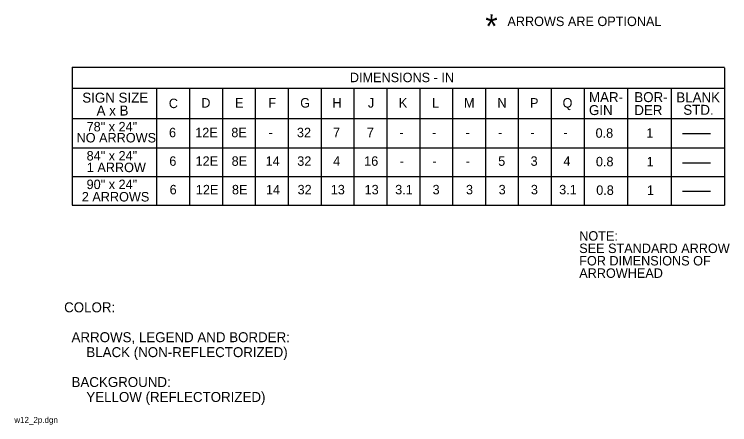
# Model space of a CAD drawing. Extents: x 0.013 to 0.2, y 0.004 to 0.259.
# Drawn here: x 0.0126 to 0.1921, y 0.0039 to 0.1069 of the extents above; entities that cross this region are included whole.
import ezdxf

# ---------------------------------------------------------------- set-up
doc = ezdxf.new("R2010")
doc.units = 0
doc.layers.add('1', color=7, linetype='Continuous')
doc.layers.add('3', color=7, linetype='Continuous')

msp = doc.modelspace()

# ---------------------------------------------------------------- linework, layer by layer
at = {"layer": '1'}
for p, q in [((0.1802803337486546, 0.07695145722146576), (0.18728598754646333, 0.07695145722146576)), ((0.1802803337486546, 0.069656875), (0.18728598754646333, 0.069656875)), ((0.1802803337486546, 0.06249062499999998), (0.18728598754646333, 0.06249062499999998))]:
    msp.add_line(p, q, dxfattribs=at)
at = {"layer": '3'}
for p, q in [((0.02711153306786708, 0.09362537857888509), (0.02711153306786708, 0.05903539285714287)), ((0.02711153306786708, 0.09362537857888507), (0.19078375, 0.09362537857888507)), ((0.19078375, 0.09343509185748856), (0.19078375, 0.05903539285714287)), ((0.19078375, 0.08824059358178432), (0.02711153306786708, 0.08824059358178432)), ((0.048336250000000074, 0.08824059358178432), (0.048336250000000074, 0.05903539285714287)), ((0.056586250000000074, 0.08824059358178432), (0.056586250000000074, 0.05903539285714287)), ((0.06483625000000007, 0.08824059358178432), (0.06483625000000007, 0.05903539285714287)), ((0.07308625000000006, 0.08824059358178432), (0.07308625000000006, 0.05903539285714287)), ((0.08133625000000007, 0.08824059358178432), (0.08133625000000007, 0.05903539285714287)), ((0.08958625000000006, 0.08824059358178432), (0.08958625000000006, 0.05903539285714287)), ((0.09783625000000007, 0.08824059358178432), (0.09783625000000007, 0.05903539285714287)), ((0.10608625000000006, 0.08824059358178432), (0.10608625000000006, 0.05903539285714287)), ((0.11433625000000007, 0.08824059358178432), (0.11433625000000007, 0.05903539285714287)), ((0.12258625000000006, 0.08824059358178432), (0.12258625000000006, 0.05903539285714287)), ((0.13083625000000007, 0.08824059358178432), (0.13083625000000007, 0.05903539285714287)), ((0.13908625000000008, 0.08824059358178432), (0.13908625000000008, 0.05903539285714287)), ((0.14733625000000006, 0.08824059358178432), (0.14733625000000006, 0.05903539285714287)), ((0.15558625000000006, 0.08824059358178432), (0.15558625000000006, 0.05903539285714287)), ((0.16646614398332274, 0.08824059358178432), (0.16646614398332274, 0.05903539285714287)), ((0.17739931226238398, 0.08824059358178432), (0.17739931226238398, 0.05903539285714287)), ((0.02711153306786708, 0.08074164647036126), (0.19078375, 0.08074164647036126)), ((0.02711153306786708, 0.07336664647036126), (0.19078374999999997, 0.07336664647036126)), ((0.02711153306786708, 0.06620101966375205), (0.19078375, 0.06620101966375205)), ((0.02711153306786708, 0.05903539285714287), (0.19078375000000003, 0.05903539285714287))]:
    msp.add_line(p, q, dxfattribs=at)

# ---------------------------------------------------------------- texts
at = {"layer": '1'}
for s, height, p in [('COLOR:', 0.0024997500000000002, (0.025125, 0.032125)), ('  ARROWS, LEGEND AND BORDER:', 0.0024997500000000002, (0.025125, 0.0246255)), ('      BLACK (NON-REFLECTORIZED)', 0.0024997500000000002, (0.025125, 0.020875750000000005)), ('  BACKGROUND:', 0.0024997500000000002, (0.025125, 0.01337625)), ('      YELLOW (REFLECTORIZED)', 0.0024997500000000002, (0.025125, 0.0096265)), ('w12_2p.dgn', 0.0015, (0.012625, 0.004375))]:
    msp.add_text(s, height=height, dxfattribs=at).set_placement(p)
at = {"layer": '3'}
for s, height, p in [('*', 0.005938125, (0.1308078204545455, 0.10095766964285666)), ('SIGN SIZE', 0.0024997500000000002, (0.0296778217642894, 0.08474164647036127)), ('MAR-', 0.0024997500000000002, (0.1568140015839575, 0.08486664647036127)), ('BOR-', 0.0024997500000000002, (0.1681890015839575, 0.08486664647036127)), ('BLANK', 0.0024997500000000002, (0.17873442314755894, 0.08480675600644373)), ('C', 0.0023752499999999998, (0.05139241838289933, 0.08336142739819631)), ('D', 0.0023752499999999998, (0.05954505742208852, 0.08349164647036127)), ('F', 0.0023752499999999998, (0.07637897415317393, 0.08349164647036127)), ('G', 0.0023752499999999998, (0.08435755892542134, 0.08349164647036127)), ('H', 0.0023752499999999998, (0.09244311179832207, 0.08349164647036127)), ('J', 0.0023752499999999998, (0.10135498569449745, 0.08349164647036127)), ('K', 0.0023752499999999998, (0.10909340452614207, 0.08349164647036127)), ('L', 0.0023752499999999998, (0.11743815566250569, 0.08349164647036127)), ('M', 0.0023752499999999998, (0.12545967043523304, 0.08349164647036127)), ('N', 0.0023752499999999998, (0.1338404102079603, 0.08349164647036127)), ('P', 0.0023752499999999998, (0.14202288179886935, 0.08349164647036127)), ('Q', 0.0023752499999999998, (0.15019089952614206, 0.08349164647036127)), ('A x B', 0.0024997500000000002, (0.033274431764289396, 0.08149189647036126)), ('GIN', 0.0024997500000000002, (0.1568140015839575, 0.08161664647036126)), ('DER', 0.0024997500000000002, (0.1681890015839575, 0.08161664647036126)), ('STD.', 0.0024997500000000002, (0.18048442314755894, 0.08168175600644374)), ('78" x 24"', 0.0023752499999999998, (0.03076183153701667, 0.07751678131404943)), ('6', 0.0023752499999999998, (0.051439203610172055, 0.07604862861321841)), ('12E', 0.0023752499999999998, (0.058016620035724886, 0.07604862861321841)), ('1', 0.0023752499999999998, (0.1712011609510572, 0.07591840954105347)), ('NO ARROWS', 0.0023752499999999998, (0.028246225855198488, 0.07474083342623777)), ('-', 0.0023752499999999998, (0.07641172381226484, 0.07604862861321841)), ('84" x 24"', 0.0023752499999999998, (0.03076183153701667, 0.07021839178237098)), ('6', 0.0023752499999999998, (0.05151816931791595, 0.06888300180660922)), ('12E', 0.0023752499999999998, (0.05809558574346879, 0.06888300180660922)), ('14', 0.0023752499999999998, (0.07568382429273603, 0.06888300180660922)), ('1', 0.0023752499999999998, (0.17128012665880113, 0.06875278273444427)), ('1 ARROW', 0.0023752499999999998, (0.03081869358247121, 0.06729428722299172)), ('90" x 24"', 0.0023752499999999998, (0.03076183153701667, 0.06304069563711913)), ('6', 0.0023752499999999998, (0.05159713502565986, 0.061717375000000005)), ('12E', 0.0023752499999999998, (0.0581745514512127, 0.06171737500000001)), ('14', 0.0023752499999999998, (0.07576279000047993, 0.06171737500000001)), ('1', 0.0023752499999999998, (0.17135909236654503, 0.061587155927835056)), ('2 ARROWS', 0.0023752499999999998, (0.02955261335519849, 0.05993199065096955))]:
    msp.add_text(s, height=height, dxfattribs=at).set_placement(p)
for s, p in [('ARROWS ARE OPTIONAL', (0.13634794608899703, 0.10394219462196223)), ('DIMENSIONS - IN', (0.09682791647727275, 0.08986664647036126)), ('E', (0.06800958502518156, 0.08349164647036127)), ('8E', (0.06707388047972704, 0.07604862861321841)), ('32', (0.08353989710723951, 0.07604862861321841)), ('7', (0.09258670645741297, 0.07604862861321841)), ('7', (0.10107895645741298, 0.07604862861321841)), ('0.8', (0.15847262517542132, 0.07591840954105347)), ('-', (0.10926471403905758, 0.07604862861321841)), ('-', (0.11745471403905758, 0.07604862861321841)), ('-', (0.12583971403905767, 0.07604862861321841)), ('-', (0.13402971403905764, 0.07604862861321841)), ('-', (0.1421222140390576, 0.07604862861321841)), ('-', (0.1504097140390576, 0.07604862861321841)), ('8E', (0.06715284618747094, 0.06888300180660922)), ('32', (0.08361886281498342, 0.06888300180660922)), ('4', (0.09261852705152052, 0.06888300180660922)), ('16', (0.10040252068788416, 0.06888300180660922)), ('5', (0.13403598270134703, 0.06888300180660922)), ('3', (0.14216015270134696, 0.06888300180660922)), ('4', (0.15040158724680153, 0.06888300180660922)), ('0.8', (0.1585515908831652, 0.06875278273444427)), ('-', (0.1093436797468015, 0.06888300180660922)), ('-', (0.1175336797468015, 0.06888300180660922)), ('-', (0.12591867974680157, 0.06888300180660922)), ('8E', (0.06723181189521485, 0.061717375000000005)), ('32', (0.08369782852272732, 0.06171737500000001)), ('13', (0.09202378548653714, 0.06171737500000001)), ('13', (0.10051603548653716, 0.06171737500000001)), ('3.1', (0.10819039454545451, 0.06171737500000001)), ('3', (0.11757161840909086, 0.06171737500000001)), ('3', (0.12595661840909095, 0.06171737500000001)), ('3', (0.13414661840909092, 0.06171737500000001)), ('3', (0.14223911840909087, 0.06171737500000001)), ('3.1', (0.1493353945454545, 0.06171737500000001)), ('0.8', (0.15863055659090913, 0.061587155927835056)), ('NOTE:', (0.15436745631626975, 0.05010456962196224)), ('SEE STANDARD ARROW', (0.15436745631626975, 0.04699083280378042)), ('FOR DIMENSIONS OF', (0.15436745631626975, 0.04387709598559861)), ('ARROWHEAD', (0.15436745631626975, 0.04076335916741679))]:
    msp.add_text(s, height=0.0023752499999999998, rotation=360, dxfattribs=at).set_placement(p)

doc.saveas('drawing.dxf')
